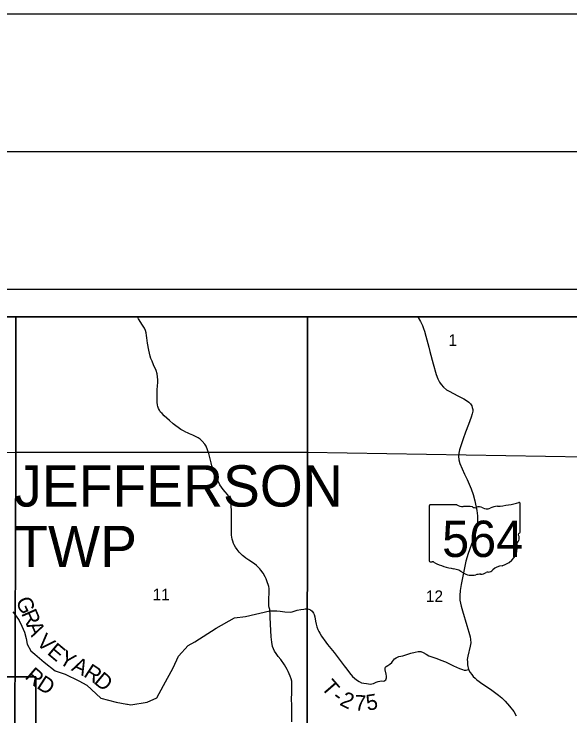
# Model space of a CAD drawing. Extents: x 0 to 34, y 0 to 22.
# Drawn here: x 4.406 to 6.424, y 19.45 to 22 of the extents above; entities that cross this region are included whole.
import ezdxf

# ---------------------------------------------------------------- set-up
doc = ezdxf.new("R2010")
doc.units = 0
for name, color, linetype in [('GM_X_Corporation', 7, 'Continuous'), ('GM_X_County_Road', 7, 'Continuous'), ('GM_X_Section_Text', 7, 'Continuous'), ('GM_X_State_Location', 7, 'Continuous'), ('GM_X_State_Route', 7, 'Continuous'), ('GM_X_State_Shield', 7, 'Continuous'), ('GM_X_Township_Road', 7, 'Continuous'), ('GM_X_Township_Road_Text', 7, 'Continuous'), ('GM_X_Township_Text', 7, 'Continuous'), ('SH_Border', 7, 'Continuous'), ('SH_Cut_Line', 7, 'Continuous'), ('SH_Data', 7, 'Continuous'), ('SH_Text', 7, 'Continuous')]:
    doc.layers.add(name, color=color, linetype=linetype)

msp = doc.modelspace()

# ---------------------------------------------------------------- linework, layer by layer
at = {"layer": 'GM_X_Corporation'}
for points in [[(4.4126, 20.9), (3.3964, 20.9), (3.3928, 20.4074), (4.4129, 20.4084)], [(5.4715, 20.9), (4.4126, 20.9), (4.4129, 20.4084), (5.4711, 20.4076)], [(6.4812, 20.9), (5.4715, 20.9), (5.4711, 20.4076), (6.4797, 20.3917), (6.481, 20.8366)], [(3.3928, 20.4074), (4.4129, 20.4084), (4.4084, 19.4053), (3.384, 19.4149)], [(5.4711, 20.4076), (5.4696, 19.395), (4.4084, 19.4053), (4.4129, 20.4084)], [(6.4797, 20.3917), (6.4778, 19.8399), (6.4758, 19.3912), (5.4696, 19.395), (5.4711, 20.4076)]]:
    msp.add_lwpolyline(points, close=True, dxfattribs=at)
at = {"layer": 'GM_X_County_Road'}
msp.add_line((5.8733, 20.8971), (5.8769, 20.9), dxfattribs=at)
at = {"layer": 'GM_X_State_Route'}
for points in [[(5.8707, 20.9), (5.8733, 20.8971), (5.8818, 20.8829), (5.8856, 20.8758), (5.8887, 20.8688), (5.8924, 20.8574), (5.8957, 20.8475), (5.9007, 20.83), (5.9113, 20.7901), (5.9156, 20.7741), (5.9277, 20.7291), (5.9389, 20.6907), (5.9449, 20.6748), (5.9512, 20.6627), (5.9568, 20.654), (5.9646, 20.6448), (5.9764, 20.6345), (5.9854, 20.6294), (6.0175, 20.6125), (6.0384, 20.6017), (6.0482, 20.5962), (6.0568, 20.5903), (6.0631, 20.5837), (6.0678, 20.5768), (6.0698, 20.5706), (6.0712, 20.5635), (6.0712, 20.5567), (6.0695, 20.5469), (6.0653, 20.5348), (6.0556, 20.5084), (6.0454, 20.4808)], [(6.0454, 20.4808), (6.0363, 20.4561), (6.0291, 20.4347), (6.0238, 20.4167), (6.0208, 20.4042), (6.02, 20.3942), (6.0213, 20.3799), (6.0242, 20.3675), (6.0412, 20.3282), (6.0506, 20.3092), (6.065, 20.2752), (6.0724, 20.2545), (6.0785, 20.2315), (6.0861, 20.1966), (6.0884, 20.1774), (6.0887, 20.1571), (6.0862, 20.1351), (6.0817, 20.1137), (6.0549, 20.0398), (6.0464, 20.0123), (6.0294, 19.927), (6.0258, 19.905), (6.0247, 19.8871), (6.025, 19.8706), (6.0287, 19.8491), (6.0336, 19.8319), (6.0499, 19.7784), (6.0574, 19.7542), (6.0617, 19.7375), (6.0637, 19.7281), (6.0642, 19.7154), (6.0624, 19.7028), (6.0534, 19.6673), (6.0516, 19.6547), (6.052, 19.6465), (6.0528, 19.6352), (6.0553, 19.6188), (6.0621, 19.6081), (6.0678, 19.5999), (6.0732, 19.593), (6.0797, 19.5867), (6.0856, 19.5811), (6.1081, 19.5652), (6.136, 19.5466), (6.1653, 19.5253), (6.1768, 19.515), (6.1887, 19.503), (6.2046, 19.4857), (6.2203, 19.466), (6.2292, 19.4496)]]:
    msp.add_lwpolyline(points, dxfattribs=at)
at = {"layer": 'GM_X_State_Shield'}
for p, q in [((5.9136, 20.2134), (5.9136, 20.0133)), ((6.0134, 20.2169), (5.9169, 20.2169)), ((6.2432, 20.1171), (6.2432, 20.2218)), ((6.2432, 20.1172), (6.2432, 20.1171))]:
    msp.add_line(p, q, dxfattribs=at)
for centre, major_axis, start_param, end_param in [((6.1258, 20.4897), (0.3495, 0), 4.814394, 5.042369), ((6.2396, 20.2223), (0.00367, 0), 6.141152, 7.989035), ((5.9174, 20.2139), (0.00382, 0), 1.712693, 3.28349), ((6.0364, 20.2401), (0.037, 0), 4.042523, 4.731795), ((6.0487, 20.1045), (0.133, 0), 1.404758, 1.657858), ((6.0788, 20.2149), (0.0107, 0), 3.836095, 5.185415), ((6.0945, 20.1918), (0.0222, 0), 0.950623, 2.079405), ((6.1232, 20.2235), (0.0267, 0), 4.081561, 5.145723), ((6.1704, 20.1558), (0.0703, 0), 1.699011, 2.107814), ((6.2424, 20.1095), (0.00568, 0), 1.883978, 3.671073), ((6.2062, 20.0962), (0.0341, 0), 5.934695, 6.695948), ((6.2393, 20.1167), (0.00393, 0), 5.05454, 6.418171), ((6.1454, 20.06), (0.0874, 0), 5.101752, 6.440018), ((6.2564, 20.0733), (0.0248, 0), 2.387724, 3.262537), ((5.9174, 20.0129), (0.00385, 0), 3.00124, 4.508301), ((5.918, 20.0333), (0.0294, 0), 4.665946, 4.897461), ((5.924, 20.0018), (0.0106, 0), 0.519207, 1.627899), ((6.0579, 20.1816), (0.2524, 0), 4.195997, 4.488961), ((6.1822, 19.9571), (0.0479, 0), 1.647645, 2.488434), ((5.9826, 19.9234), (0.079, 0), 0.823519, 1.323587), ((6.068, 20.0008), (0.0501, 0), 4.026481, 4.996735), ((6.1006, 19.9858), (0.0267, 0), 4.691044, 5.507374), ((6.1248, 19.9664), (0.00752, 0), 1.147584, 2.315152), ((6.1216, 19.9939), (0.0282, 0), 4.937069, 5.64225), ((6.097, 19.9316), (0.0412, 0), 1.495662, 1.94098)]:
    msp.add_ellipse(centre, major_axis=major_axis, ratio=0.8, start_param=start_param, end_param=end_param, dxfattribs=at)
at = {"layer": 'GM_X_Township_Road'}
for points in [[(5.4149, 19.4286), (5.4142, 19.4507), (5.4139, 19.4881), (5.4138, 19.5124), (5.4141, 19.532), (5.4148, 19.564), (5.414, 19.5758), (5.4122, 19.5848), (5.4087, 19.5941), (5.4013, 19.6116), (5.3978, 19.6188), (5.3883, 19.6349), (5.3743, 19.6544), (5.3652, 19.6662), (5.3574, 19.6765), (5.352, 19.6855), (5.3479, 19.6934), (5.3446, 19.7026), (5.3413, 19.7182), (5.3392, 19.7376), (5.3385, 19.7608), (5.3358, 19.8074), (5.3357, 19.8212), (5.3351, 19.8315), (5.3341, 19.8362), (5.3325, 19.8432), (5.3314, 19.8499), (5.3306, 19.8587), (5.3305, 19.8692), (5.3313, 19.8795), (5.3325, 19.8939), (5.3325, 19.9037), (5.3319, 19.9127), (5.331, 19.9198), (5.3291, 19.9273), (5.3266, 19.9337), (5.3211, 19.9475), (5.3172, 19.9553), (5.31, 19.9682), (5.3019, 19.9793), (5.2981, 19.9843), (5.2935, 19.9891), (5.2857, 19.9963), (5.2787, 20.0023), (5.2581, 20.0163), (5.2473, 20.0236), (5.2408, 20.0285), (5.2356, 20.0327), (5.2284, 20.0394), (5.2231, 20.0447), (5.2157, 20.0543), (5.2101, 20.0624), (5.205, 20.071), (5.2024, 20.0767), (5.1998, 20.0848), (5.198, 20.0918), (5.1966, 20.0996), (5.1955, 20.1069), (5.1954, 20.123), (5.1956, 20.1406), (5.1952, 20.1826), (5.1952, 20.1911), (5.1949, 20.2003), (5.1945, 20.2086), (5.1937, 20.2155), (5.1931, 20.2217), (5.1921, 20.2267), (5.1905, 20.2333), (5.1867, 20.2436), (5.1811, 20.2538), (5.1724, 20.2643), (5.1649, 20.273), (5.1588, 20.2808), (5.1533, 20.289), (5.1456, 20.3054), (5.1419, 20.3139), (5.1391, 20.3206), (5.1344, 20.333), (5.1294, 20.3464), (5.1246, 20.359), (5.1213, 20.369), (5.1151, 20.3938), (5.1129, 20.4034), (5.1113, 20.4089), (5.1089, 20.4163), (5.1033, 20.4295), (5.0985, 20.4372), (5.0894, 20.4479), (5.0818, 20.4548), (5.0749, 20.46), (5.0545, 20.4704), (5.0428, 20.475), (5.0356, 20.478), (5.0292, 20.4809), (5.021, 20.4853), (5.0121, 20.4909), (4.9837, 20.5117), (4.9702, 20.5227), (4.9508, 20.5399), (4.9433, 20.5482), (4.9383, 20.5539), (4.9337, 20.561), (4.9307, 20.5668), (4.9284, 20.5737), (4.9272, 20.5793), (4.926, 20.5902), (4.9258, 20.6041), (4.9258, 20.6222), (4.9261, 20.6342), (4.9273, 20.6496), (4.9283, 20.6618), (4.9281, 20.6711), (4.9272, 20.6816), (4.9253, 20.6929), (4.9216, 20.705), (4.9128, 20.7251), (4.9071, 20.739), (4.9029, 20.7485), (4.9001, 20.7565), (4.8948, 20.7787), (4.8904, 20.8045), (4.8884, 20.8237), (4.8873, 20.8326), (4.8853, 20.8419), (4.883, 20.85), (4.8792, 20.8583), (4.8725, 20.8692), (4.8583, 20.8922), (4.8537, 20.9)], [(4.401, 19.8278), (4.4141, 19.8117), (4.4246, 19.7964), (4.4347, 19.7757), (4.4444, 19.7547), (4.4506, 19.7314), (4.4532, 19.7107), (4.4668, 19.6866), (4.4815, 19.674), (4.5158, 19.6456), (4.5551, 19.6137), (4.5919, 19.6014), (4.6407, 19.5778), (4.6704, 19.561), (4.7212, 19.5147), (4.7763, 19.4996), (4.816, 19.4929)], [(4.816, 19.4929), (4.8179, 19.4926), (4.8302, 19.4905), (4.8889, 19.4993), (4.9241, 19.5155), (4.9491, 19.5609), (4.9835, 19.6242), (5.0029, 19.6665), (5.0379, 19.7055), (5.0621, 19.7193), (5.1402, 19.7689), (5.2059, 19.8066), (5.246, 19.8111), (5.3351, 19.8315)], [(5.3351, 19.8315), (5.34, 19.8318), (5.3485, 19.8322), (5.3597, 19.8314), (5.3726, 19.8302), (5.3889, 19.8283), (5.4084, 19.8273), (5.4156, 19.8285), (5.4337, 19.8336), (5.4474, 19.8362), (5.4584, 19.8381), (5.4634, 19.8386), (5.4702, 19.8384), (5.476, 19.8374), (5.482, 19.8348), (5.4879, 19.8309), (5.4935, 19.8237), (5.496, 19.8183), (5.4976, 19.8104), (5.5006, 19.794), (5.5032, 19.783), (5.5057, 19.773), (5.509, 19.7635), (5.5121, 19.7566), (5.5159, 19.75), (5.5226, 19.7401), (5.5378, 19.7179), (5.5437, 19.7099), (5.5501, 19.7017), (5.5678, 19.6803), (5.5827, 19.6607), (5.6046, 19.632), (5.6136, 19.6201), (5.6235, 19.6066), (5.6349, 19.5928), (5.6495, 19.581), (5.6587, 19.5744), (5.667, 19.5702), (5.6765, 19.5684), (5.6854, 19.5672), (5.6995, 19.5655), (5.705, 19.5661), (5.7111, 19.5675), (5.7159, 19.5697), (5.721, 19.572), (5.7274, 19.5745), (5.7335, 19.5761), (5.7412, 19.5768), (5.7486, 19.5766), (5.7527, 19.5781), (5.7559, 19.5813), (5.758, 19.5882), (5.7579, 19.5943), (5.7571, 19.601), (5.7537, 19.6169), (5.7538, 19.623), (5.7547, 19.6266), (5.757, 19.6296), (5.7628, 19.6334), (5.7705, 19.6377), (5.7774, 19.6439), (5.7802, 19.6475), (5.7832, 19.6525), (5.7872, 19.6575), (5.7932, 19.6615), (5.8026, 19.6655), (5.8176, 19.6685), (5.847, 19.6779), (5.8624, 19.6821), (5.8729, 19.684), (5.8828, 19.6838), (5.8913, 19.6805), (5.9018, 19.6746), (5.9123, 19.6685), (5.9404, 19.6582), (5.9553, 19.6524), (5.9728, 19.6462), (5.9867, 19.6394), (6.0009, 19.6317), (6.0228, 19.6221), (6.0337, 19.6186), (6.0406, 19.6165), (6.0473, 19.6163), (6.0553, 19.6188)]]:
    msp.add_lwpolyline(points, dxfattribs=at)
at = {"layer": 'GM_X_Township_Text'}
msp.add_lwpolyline([(6.4525, 17.3965), (6.4653, 18.1777), (6.4655, 18.1862), (6.4767, 18.8745), (6.4767, 18.8755), (6.4827, 20.9), (2.1, 20.9), (2.1, 19.4241)], dxfattribs=at)
at = {"layer": 'SH_Border'}
msp.add_lwpolyline([(1.5, 21.5), (33.5, 21.5), (33.5, 0.5), (1.5, 0.5)], close=True, dxfattribs=at)
at = {"layer": 'SH_Cut_Line'}
msp.add_lwpolyline([(0, 0), (34, 0), (34, 22), (0, 22)], close=True, dxfattribs=at)
at = {"layer": 'SH_Data'}
for p, q in [((2, 21), (9, 21)), ((2.1, 20.9), (8.9, 20.9))]:
    msp.add_line(p, q, dxfattribs=at)
at = {"layer": 'SH_Text'}
for points in [[(4.4854, 19.5924), (2.4095, 19.5924), (2.4095, 18.4935), (4.4854, 18.4935)], [(2.4095, 19.5924), (4.4854, 19.5924), (4.4854, 18.4935), (2.4095, 18.4935)]]:
    msp.add_lwpolyline(points, close=True, dxfattribs=at)

# ---------------------------------------------------------------- texts
at = {"layer": 'GM_X_Section_Text'}
for s, height, p in [('1', 0.0419, (5.9833, 20.7944)), ('11', 0.04186, (4.9091, 19.8702)), ('12', 0.04186, (5.9012, 19.8639))]:
    msp.add_text(s, height=height, rotation=0, dxfattribs=at).set_placement(p)
at = {"layer": 'GM_X_State_Location'}
for s in ['s', 'r']:
    msp.add_text(s, height=0.000189, dxfattribs=at).set_placement((6.0747, 20.1001))
msp.add_text('564', height=0.000189, rotation=0, dxfattribs=at).set_placement((6.0079, 20.0863))
at = {"layer": 'GM_X_State_Shield'}
msp.add_text('564', height=0.13184, dxfattribs=at).set_placement((5.9601, 20.0274))
at = {"layer": 'GM_X_Township_Road_Text'}
for s, rotation, p in [('G', 294.4777, (4.4107, 19.8678)), ('R', 293.7659, (4.4313, 19.8224)), ('A', 293.212, (4.4501, 19.7799)), ('V', 316.4995, (4.4841, 19.7134)), ('E', 319.9548, (4.5232, 19.6765)), ('Y', 330.452, (4.565, 19.6426)), ('A', 333.7813, (4.6117, 19.6163)), ('R', 326.9768, (4.655, 19.5951)), ('R', 319.2484, (4.4425, 19.5885)), ('D', 327.1787, (4.4846, 19.553)), ('D', 320.2131, (4.6927, 19.5707)), ('T', 310.8356, (5.5185, 19.5518)), ('2', 333.9358, (5.5849, 19.4909)), ('-', 324.5106, (5.5572, 19.5097)), ('7', 358.2298, (5.6417, 19.4693)), ('5', 9.1576, (5.6884, 19.4689))]:
    msp.add_text(s, height=0.0568, rotation=rotation, dxfattribs=at).set_placement(p)
at = {"layer": 'GM_X_Township_Text'}
for s, p in [('JEFFERSON', (4.4068, 20.2105)), ('TWP', (4.4068, 19.9905))]:
    msp.add_text(s, height=0.15, rotation=0, dxfattribs=at).set_placement(p)

doc.saveas('drawing.dxf')
